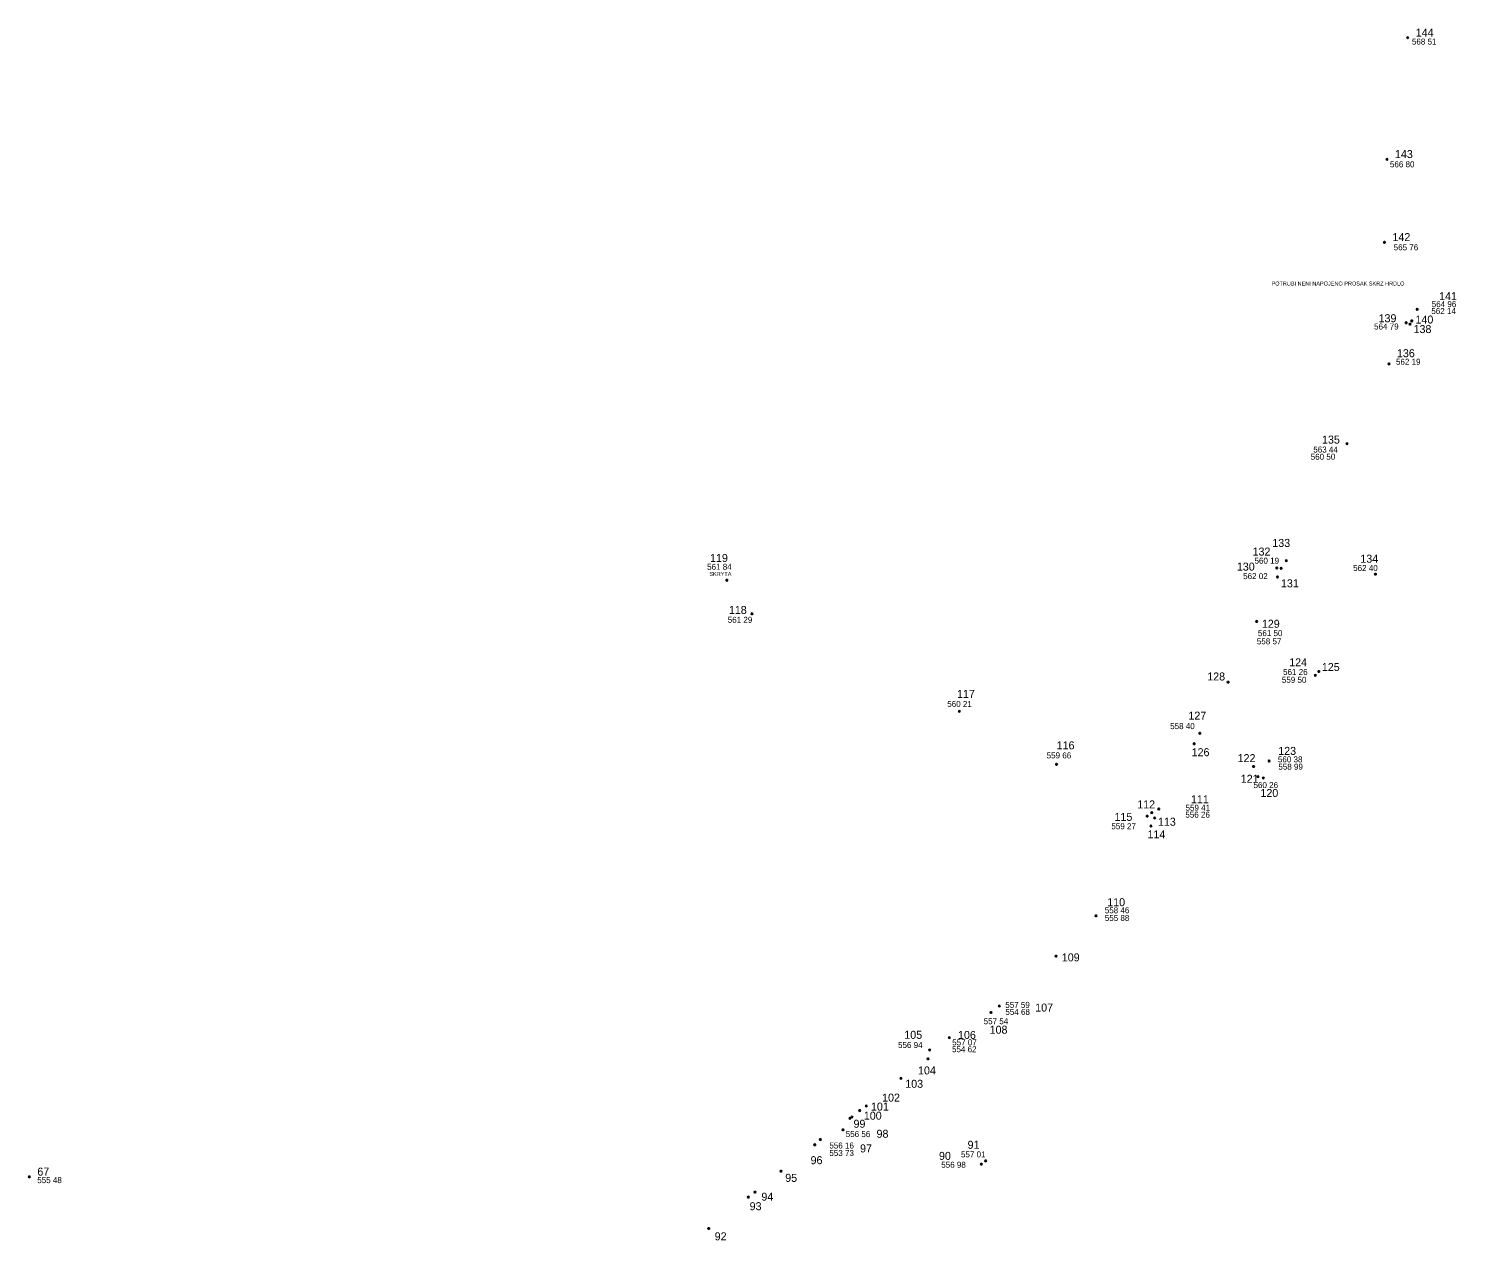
# Model space of a CAD drawing. Extents: x -710806 to -710046, y -1116918 to -1116046.
# Drawn here: x -710471.7 to -710293.2, y -1116479.3 to -1116327.7 of the extents above; entities that cross this region are included whole.
import ezdxf
from ezdxf.enums import TextEntityAlignment as Align

# ---------------------------------------------------------------- set-up
doc = ezdxf.new("R2010")
doc.units = 0
doc.header["$LTSCALE"] = 0.4
doc.header["$PDMODE"] = 32
doc.header["$PDSIZE"] = 0.2
for name, color, linetype in [('43', 7, 'Continuous'), ('55', 7, 'Continuous'), ('56', 7, 'Continuous')]:
    doc.layers.add(name, color=color, linetype=linetype)
doc.layers.add('63', color=7, linetype='Continuous', lineweight=13)

msp = doc.modelspace()

# ---------------------------------------------------------------- linework, layer by layer
at = {"layer": '56'}
for p in [(-710299.298, -1116328.891), (-710301.898, -1116344.085), (-710302.211, -1116354.462), (-710298.116, -1116362.85), (-710299.493, -1116364.527), (-710299.019, -1116364.701), (-710298.795, -1116364.289), (-710301.63, -1116369.663), (-710306.903, -1116379.643), (-710315.668, -1116395.194), (-710315.115, -1116395.225), (-710314.466, -1116394.262), (-710384.403, -1116396.708), (-710315.577, -1116396.297), (-710303.333, -1116395.955), (-710381.248, -1116400.906), (-710318.181, -1116401.863), (-710310.408, -1116408.122), (-710321.75, -1116409.457), (-710310.847, -1116408.606), (-710355.346, -1116413.11), (-710325.281, -1116415.845), (-710325.996, -1116417.159), (-710343.193, -1116419.719), (-710318.571, -1116420.002), (-710316.618, -1116419.317), (-710318.023, -1116421.263), (-710317.337, -1116421.443), (-710331.29, -1116425.767), (-710330.414, -1116425.31), (-710331.87, -1116426.209), (-710331.378, -1116427.434), (-710330.924, -1116426.426), (-710338.256, -1116438.666), (-710343.25, -1116443.707), (-710351.391, -1116450.749), (-710350.334, -1116449.934), (-710356.594, -1116453.887), (-710359.054, -1116455.445), (-710359.249, -1116456.542), (-710362.625, -1116458.975), (-710367.803, -1116463.009), (-710366.958, -1116462.43), (-710369.004, -1116463.988), (-710368.747, -1116463.829), (-710372.719, -1116466.635), (-710369.875, -1116465.42), (-710373.409, -1116467.289), (-710377.635, -1116470.591), (-710352.581, -1116469.715), (-710352.049, -1116469.302), (-710471.573, -1116471.295), (-710381.721, -1116473.834), (-710380.891, -1116473.208), (-710386.657, -1116477.76)]:
    msp.add_point(p, dxfattribs=at)

# ---------------------------------------------------------------- texts
at = {"layer": '43'}
for s, p in [('568 51 ', (-710297.1042, -1116329.746)), ('566 80 ', (-710299.8512, -1116345.085)), ('565 76 ', (-710299.3842, -1116355.466)), ('564 96 ', (-710294.6242, -1116362.572)), ('564 79 ', (-710301.8332, -1116365.366)), ('562 19 ', (-710299.0972, -1116369.773)), ('563 44 ', (-710309.4302, -1116380.747)), ('561 84 ', (-710385.1872, -1116395.411)), ('560 19 ', (-710316.7772, -1116394.639)), ('562 40 ', (-710304.4482, -1116395.557)), ('562 02 ', (-710318.1952, -1116396.571)), ('561 29 ', (-710382.6132, -1116402.035)), ('561 50 ', (-710316.3522, -1116403.699)), ('561 26 ', (-710313.2052, -1116408.554)), ('560 21 ', (-710355.1782, -1116412.55)), ('558 40 ', (-710327.3172, -1116415.325)), ('559 66 ', (-710342.7522, -1116418.985)), ('560 38 ', (-710313.8522, -1116419.481)), ('560 26 ', (-710316.9022, -1116422.699)), ('559 41 ', (-710325.4012, -1116425.525)), ('559 27 ', (-710334.6652, -1116427.838)), ('558 46 ', (-710335.4882, -1116438.346)), ('557 59 ', (-710347.9272, -1116450.175)), ('557 54 ', (-710350.6282, -1116452.217)), ('556 94 ', (-710361.3302, -1116455.19)), ('557 07 ', (-710354.5582, -1116454.865)), ('556 56 ', (-710367.8662, -1116466.328)), ('556 16 ', (-710369.9092, -1116467.755)), ('557 01 ', (-710353.4622, -1116468.863)), ('556 98 ', (-710355.9282, -1116470.165)), ('555 48 ', (-710468.9112, -1116472.084))]:
    msp.add_text(s, height=0.75, dxfattribs=at).set_placement(p, align=Align.CENTER)
for s, p in [('562 14', (-710296.352, -1116363.435)), ('560 50', (-710311.425, -1116381.651)), ('558 57', (-710318.156, -1116404.721)), ('559 50', (-710315.029, -1116409.537)), ('558 99', (-710315.47, -1116420.397)), ('556 26', (-710327.093, -1116426.394)), ('555 88', (-710337.16, -1116439.31)), ('554 68', (-710349.589, -1116451.053)), ('554 62', (-710356.257, -1116455.719)), ('553 73', (-710371.586, -1116468.696))]:
    msp.add_text(s, height=0.75, dxfattribs=at).set_placement(p)
at = {"layer": '55'}
for s, p in [('144', (-710298.298, -1116328.741)), ('143', (-710300.898, -1116343.935)), ('142', (-710301.211, -1116354.312)), ('141', (-710295.378, -1116361.695)), ('139', (-710302.946, -1116364.457)), ('138', (-710298.571, -1116365.814)), ('140', (-710298.332, -1116364.616)), ('136', (-710300.647, -1116368.831)), ('135', (-710310.014, -1116379.633)), ('133', (-710316.226, -1116392.547)), ('119', (-710386.501, -1116394.429)), ('132', (-710318.692, -1116393.629)), ('134', (-710305.224, -1116394.52)), ('130', (-710320.655, -1116395.509)), ('131', (-710315.144, -1116397.602)), ('118', (-710384.146, -1116400.927)), ('129', (-710317.528, -1116402.653)), ('124', (-710314.113, -1116407.471)), ('125', (-710310.033, -1116408.062)), ('128', (-710324.358, -1116409.244)), ('117', (-710355.63, -1116411.421)), ('127', (-710326.711, -1116414.14)), ('116', (-710343.181, -1116417.856)), ('126', (-710326.309, -1116418.714)), ('122', (-710320.561, -1116419.452)), ('123', (-710315.483, -1116418.547)), ('121', (-710320.176, -1116422.032)), ('111', (-710326.399, -1116424.606)), ('120', (-710317.712, -1116423.809)), ('115', (-710335.947, -1116426.793)), ('112', (-710333.108, -1116425.237)), ('113', (-710330.521, -1116427.403)), ('114', (-710331.825, -1116428.981)), ('110', (-710336.859, -1116437.46)), ('109', (-710342.537, -1116444.361)), ('107', (-710345.861, -1116450.638)), ('108', (-710351.557, -1116453.405)), ('105', (-710362.223, -1116454.041)), ('106', (-710355.507, -1116454.056)), ('104', (-710360.507, -1116458.494)), ('103', (-710362.105, -1116460.166)), ('102', (-710364.996, -1116461.892)), ('100', (-710367.281, -1116464.152)), ('101', (-710366.385, -1116463.016)), ('99', (-710368.569, -1116465.162)), ('98', (-710365.69, -1116466.412)), ('91', (-710354.31, -1116467.79)), ('96', (-710373.934, -1116469.719)), ('97', (-710367.748, -1116468.242)), ('90', (-710357.885, -1116469.179)), ('67', (-710470.573, -1116471.145)), ('95', (-710377.106, -1116471.926)), ('94', (-710380.081, -1116474.277)), ('93', (-710381.551, -1116475.471)), ('92', (-710385.922, -1116479.236))]:
    msp.add_text(s, height=1, dxfattribs=at).set_placement(p)
at = {"layer": '63'}
for s, p in [('POTRUBI NENI NAPOJENO PROSAK SKRZ HRDLO', (-710316.323, -1116359.867)), ('SKRYTA', (-710386.585, -1116396.175))]:
    msp.add_text(s, height=0.5, dxfattribs=at).set_placement(p)

doc.saveas('drawing.dxf')
